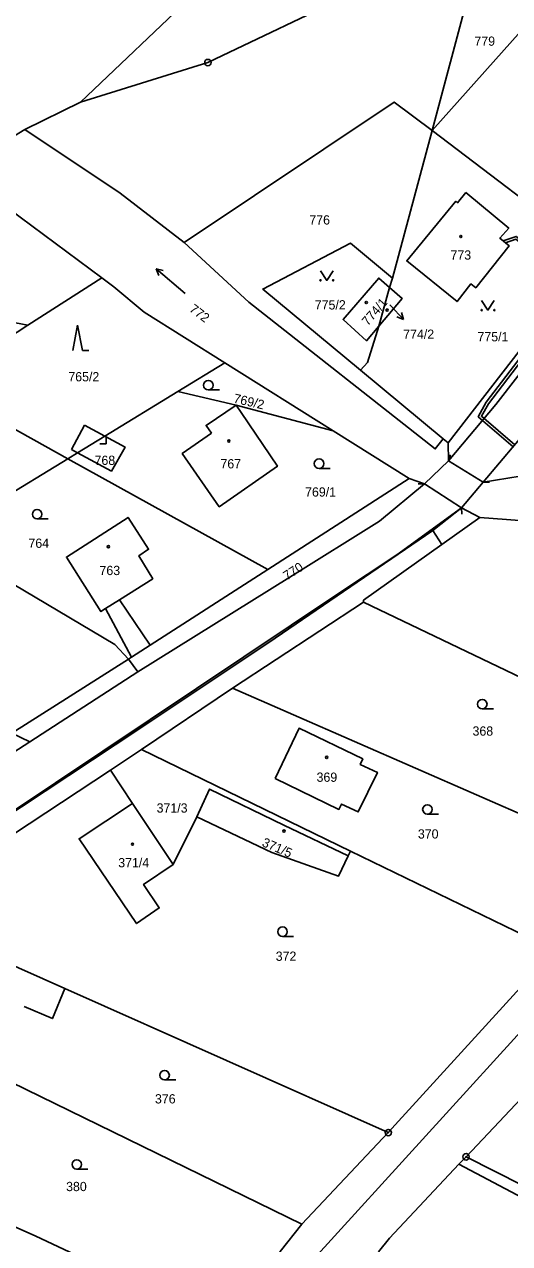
# Model space of a CAD drawing. Extents: x -587171 to -555306, y -1167727 to -1074732.
# Drawn here: x -560683.2 to -560606.6, y -1078329.1 to -1078136.7 of the extents above; entities that cross this region are included whole.
import ezdxf

# ---------------------------------------------------------------- set-up
doc = ezdxf.new("R2010")
doc.units = 0
for name, color, linetype in [('Hranice parcel', 7, 'Continuous'), ('Parcelní čísla', 7, 'Continuous'), ('Pop  PČ popisy', 7, 'Continuous'), ('Poz předměty', 7, 'Continuous'), ('Vnitřní kresba', 7, 'Continuous'), ('Věcná břemena k části', 7, 'Continuous'), ('Značky bodu BP', 7, 'Continuous'), ('Značky budov', 7, 'Continuous'), ('Značky kultur', 7, 'Continuous')]:
    doc.layers.add(name, color=color, linetype=linetype)

msp = doc.modelspace()

# ---------------------------------------------------------------- linework, layer by layer
at = {"layer": 'Hranice parcel'}
for p, q in [((-560610.78, -1078123.27), (-560618.86, -1078153.49)), ((-560599.98, -1078132.35), (-560618.86, -1078153.49)), ((-560683.18, -1078153.32), (-560674.38, -1078149)), ((-560625.08, -1078176.75), (-560618.86, -1078153.49)), ((-560670.98, -1078176.74), (-560693.82, -1078159.78)), ((-560616.33, -1078202.74), (-560593.21, -1078172.91)), ((-560670.98, -1078176.74), (-560682.66, -1078184.21)), ((-560627.26, -1078184.35), (-560625.59, -1078178.23)), ((-560625.08, -1078176.75), (-560625.59, -1078178.23)), ((-560682.66, -1078184.21), (-560697.37, -1078193.62)), ((-560659.01, -1078194.64), (-560651.59, -1078190.11)), ((-560651.59, -1078190.11), (-560634.45, -1078200.85)), ((-560617.1, -1078202.1), (-560630.14, -1078191.29)), ((-560676.37, -1078205.25), (-560697.37, -1078193.62)), ((-560670.54, -1078201.69), (-560659.01, -1078194.64)), ((-560634.45, -1078200.85), (-560622.47, -1078208.37)), ((-560674.83, -1078204.31), (-560670.54, -1078201.69)), ((-560616.33, -1078202.74), (-560617.1, -1078202.1)), ((-560676.37, -1078205.25), (-560697.03, -1078217.88)), ((-560676.37, -1078205.25), (-560674.83, -1078204.31)), ((-560644.78, -1078222.75), (-560676.37, -1078205.25)), ((-560622.47, -1078208.37), (-560644.78, -1078222.75)), ((-560620.07, -1078209.21), (-560622.47, -1078208.37)), ((-560610.79, -1078208.96), (-560614.19, -1078213.01)), ((-560611.31, -1078214.5), (-560614.19, -1078213.01)), ((-560600.9, -1078215.29), (-560611.31, -1078214.5)), ((-560663.37, -1078234.66), (-560644.78, -1078222.75)), ((-560629.67, -1078227.88), (-560650.35, -1078241.47)), ((-560629.67, -1078227.88), (-560573.72, -1078254.67)), ((-560666.3, -1078236.54), (-560663.37, -1078234.66)), ((-560666.81, -1078236.87), (-560666.3, -1078236.54)), ((-560666.81, -1078236.87), (-560665.29, -1078238.89)), ((-560682.38, -1078249.9), (-560665.29, -1078238.89)), ((-560650.35, -1078241.47), (-560664.75, -1078251.14)), ((-560650.35, -1078241.47), (-560587.14, -1078269.06)), ((-560698.04, -1078259.98), (-560682.38, -1078249.9)), ((-560664.75, -1078251.14), (-560669.63, -1078254.36)), ((-560664.75, -1078251.14), (-560631.72, -1078267.16)), ((-560669.63, -1078254.36), (-560699.58, -1078274.12)), ((-560666.15, -1078259.62), (-560669.63, -1078254.36)), ((-560666.15, -1078259.62), (-560659.76, -1078269.27)), ((-560655.99, -1078261.72), (-560659.76, -1078269.27)), ((-560631.72, -1078267.16), (-560632.08, -1078267.89)), ((-560631.72, -1078267.16), (-560599.53, -1078282.77)), ((-560691.6, -1078282.24), (-560676.82, -1078288.83)), ((-560625.76, -1078311.56), (-560599.53, -1078282.77)), ((-560676.82, -1078288.83), (-560625.76, -1078311.56)), ((-560588.9, -1078289.27), (-560613.49, -1078315.38)), ((-560691.79, -1078300.48), (-560639.44, -1078326)), ((-560639.44, -1078326), (-560625.76, -1078311.56)), ((-560614.6, -1078316.55), (-560613.49, -1078315.38))]:
    msp.add_line(p, q, dxfattribs=at)
for points in [[(-560364.68, -1077894.4), (-560366.71, -1077894.44), (-560368.49, -1077895.33), (-560369.63, -1077896.38), (-560417.05, -1077958.08), (-560457.78, -1078010.82), (-560494.61, -1078058.79), (-560557.78, -1078140.57), (-560603.03, -1078199.81), (-560610.79, -1078208.96)], [(-560674.38, -1078149), (-560656.3, -1078131.82), (-560630.87, -1078105.41), (-560608.7, -1078075.28)], [(-560605.43, -1078079.66), (-560608.74, -1078095.5), (-560617.6, -1078115.38), (-560630.82, -1078131.57), (-560654.26, -1078142.76), (-560674.38, -1078149)], [(-560618.86, -1078153.49), (-560624.82, -1078148.98), (-560658.01, -1078171.17)], [(-560693.82, -1078159.78), (-560691.9, -1078158.62), (-560686.41, -1078155.29), (-560683.18, -1078153.32)], [(-560658.01, -1078171.17), (-560668.12, -1078163.37), (-560683.18, -1078153.32)], [(-560618.86, -1078153.49), (-560594.02, -1078172.3), (-560593.21, -1078172.91)], [(-560613.51, -1078163.27), (-560614.82, -1078164.88), (-560615.09, -1078164.64), (-560622.85, -1078174.04), (-560614.89, -1078180.47), (-560612.72, -1078177.67), (-560611.95, -1078178.29), (-560606.67, -1078171.69), (-560608.17, -1078170.44), (-560606.75, -1078168.87), (-560613.51, -1078163.27)], [(-560617.1, -1078202.1), (-560618.35, -1078203.71), (-560647.77, -1078180.58), (-560658.01, -1078171.17)], [(-560630.14, -1078191.29), (-560645.58, -1078178.48), (-560631.73, -1078171.26), (-560625.08, -1078176.75)], [(-560651.59, -1078190.11), (-560664.3, -1078182.13), (-560669.11, -1078178.12), (-560670.98, -1078176.74)], [(-560625.59, -1078178.23), (-560627.28, -1078176.77), (-560632.89, -1078183.29), (-560629.2, -1078186.63), (-560627.26, -1078184.35)], [(-560627.26, -1078184.35), (-560623.55, -1078179.99), (-560625.59, -1078178.23)], [(-560682.66, -1078184.21), (-560708.94, -1078179.22), (-560716.35, -1078183.1)], [(-560627.26, -1078184.35), (-560629.07, -1078190.05), (-560630.14, -1078191.29)], [(-560634.45, -1078200.85), (-560649.79, -1078196.79), (-560659.01, -1078194.64)], [(-560653.68, -1078201.24), (-560658.3, -1078204.45), (-560652.47, -1078212.84), (-560643.27, -1078206.44), (-560648.99, -1078197.98), (-560649.79, -1078196.79), (-560654.54, -1078200.01), (-560653.68, -1078201.24)], [(-560674.83, -1078204.31), (-560669.5, -1078207.2), (-560667.33, -1078203.41), (-560670.54, -1078201.69)], [(-560620.07, -1078209.21), (-560616.23, -1078205.58), (-560616.33, -1078202.74)], [(-560665.29, -1078238.89), (-560641.31, -1078223.92), (-560627.17, -1078215.1), (-560620.07, -1078209.21)], [(-560610.79, -1078208.96), (-560606.86, -1078208.33), (-560604.94, -1078208.02)], [(-560682.38, -1078249.9), (-560685.21, -1078248.55), (-560765.59, -1078210.1)], [(-560614.19, -1078213.01), (-560624.44, -1078220.41), (-560633.62, -1078226.53), (-560693.33, -1078266.36), (-560745.67, -1078300.51), (-560764.56, -1078312.94), (-560776.56, -1078320.84), (-560789.02, -1078328.98), (-560788.94, -1078329.13)], [(-560614.19, -1078213.01), (-560618.74, -1078216.59), (-560643.65, -1078233.58), (-560665.15, -1078247.94), (-560691.05, -1078265.01), (-560721.21, -1078284.77), (-560745.49, -1078300.66), (-560767.21, -1078314.92), (-560788.94, -1078329.13)], [(-560663.37, -1078234.66), (-560668.21, -1078227.51), (-560662.96, -1078224.19), (-560665.18, -1078220.58), (-560663.61, -1078219.54), (-560666.85, -1078214.51), (-560676.59, -1078220.77), (-560671.14, -1078229.36), (-560670.4, -1078228.89), (-560666.3, -1078236.54)], [(-560611.31, -1078214.5), (-560617.29, -1078218.76), (-560629.67, -1078227.59), (-560629.67, -1078227.88)], [(-560686.84, -1078223.94), (-560668.95, -1078234.57), (-560666.81, -1078236.87)], [(-560643.61, -1078255.69), (-560633.56, -1078260.57), (-560633.17, -1078259.74), (-560630.52, -1078260.96), (-560627.49, -1078254.73), (-560630.2, -1078253.48), (-560629.79, -1078252.62), (-560639.85, -1078247.77), (-560643.61, -1078255.69)], [(-560655.99, -1078261.72), (-560653.98, -1078257.38), (-560642.25, -1078263.05), (-560632.08, -1078267.89)], [(-560659.76, -1078269.27), (-560664.41, -1078272.4), (-560661.93, -1078276.11), (-560665.51, -1078278.59), (-560674.59, -1078265.21), (-560666.15, -1078259.62)], [(-560632.08, -1078267.89), (-560633.64, -1078271.12), (-560644.18, -1078267.38), (-560655.99, -1078261.72)], [(-560683.29, -1078291.65), (-560678.8, -1078293.56), (-560676.82, -1078288.83)], [(-560627.29, -1078330.35), (-560625.56, -1078328.2), (-560614.6, -1078316.55)], [(-560385.98, -1078420.93), (-560440.99, -1078396.48), (-560509.19, -1078367.57), (-560529.93, -1078357.83), (-560576.18, -1078336.84), (-560614.6, -1078316.55)], [(-560613.49, -1078315.38), (-560586.49, -1078329.01), (-560584.41, -1078326.77)], [(-560701.89, -1078318.79), (-560681.43, -1078327.92), (-560659.37, -1078338.27), (-560653.21, -1078341.45)], [(-560653.21, -1078341.45), (-560642.85, -1078330.31), (-560639.44, -1078326)]]:
    msp.add_lwpolyline(points, dxfattribs=at)
at = {"layer": 'Pop  PČ popisy'}
for p, q in [((-560625.5, -1078180.97), (-560625.41, -1078181.07)), ((-560625.41, -1078181.07), (-560623.36, -1078183.27)), ((-560623.36, -1078183.27), (-560623.68, -1078182.19)), ((-560623.36, -1078183.27), (-560624.41, -1078182.87))]:
    msp.add_line(p, q, dxfattribs=at)
at = {"layer": 'Poz předměty'}
msp.add_line((-560637.46, -1078331.41), (-560583.59, -1078272.23), dxfattribs=at)
at = {"layer": 'Vnitřní kresba'}
for p, q in [((-560562.6, -1078136.93), (-560608.77, -1078196.7)), ((-560608.77, -1078196.7), (-560616.23, -1078205.58)), ((-560673.73, -1078199.97), (-560675.8, -1078203.79)), ((-560670.54, -1078201.69), (-560673.73, -1078199.97)), ((-560675.8, -1078203.79), (-560674.83, -1078204.31)), ((-560615.95, -1078204.62), (-560616.23, -1078205.58)), ((-560616.23, -1078205.58), (-560610.79, -1078208.96)), ((-560621.07, -1078209.23), (-560620.07, -1078209.21)), ((-560614.19, -1078213.01), (-560620.07, -1078209.21)), ((-560609.79, -1078208.94), (-560610.79, -1078208.96)), ((-560614.17, -1078214.01), (-560614.19, -1078213.01)), ((-560618.74, -1078216.59), (-560617.29, -1078218.76)), ((-560670.4, -1078228.89), (-560668.21, -1078227.51)), ((-560685.21, -1078248.55), (-560666.81, -1078236.87))]:
    msp.add_line(p, q, dxfattribs=at)
at = {"layer": 'Věcná břemena k části'}
msp.add_lwpolyline([(-560597.68, -1078176.78), (-560596.64, -1078177.33), (-560596.39, -1078177.01), (-560597.46, -1078176.45), (-560605.56, -1078170.19), (-560607.64, -1078170.88), (-560607.28, -1078171.18), (-560605.63, -1078170.63)], close=True, dxfattribs=at)
for points in [[(-560596, -1078177.67), (-560610.3, -1078196.35), (-560611.56, -1078198.63), (-560606.04, -1078203.36)], [(-560605.78, -1078203.05), (-560611.05, -1078198.54), (-560609.96, -1078196.57), (-560595.54, -1078177.72)]]:
    msp.add_lwpolyline(points, dxfattribs=at)
at = {"layer": 'Značky bodu BP'}
for centre, radius in [((-560654.26, -1078142.76), 0.5), ((-560654.26, -1078142.76), 0.0303), ((-560625.76, -1078311.56), 0.5), ((-560625.76, -1078311.56), 0.0303), ((-560613.49, -1078315.38), 0.5), ((-560613.49, -1078315.38), 0.0303)]:
    msp.add_circle(centre, radius, dxfattribs=at)
at = {"layer": 'Značky budov'}
for centre in [(-560614.31, -1078170.19), (-560629.24, -1078180.61), (-560625.95, -1078181.81), (-560650.95, -1078202.47), (-560669.96, -1078219.14), (-560635.49, -1078252.37), (-560642.23, -1078263.99), (-560666.15, -1078266.06)]:
    msp.add_circle(centre, 0.175, dxfattribs=at)
at = {"layer": 'Značky kultur'}
for p, q in [((-560657.82, -1078179.17), (-560662.42, -1078175.31)), ((-560662.42, -1078175.31), (-560661.99, -1078176.33)), ((-560662.42, -1078175.31), (-560661.34, -1078175.56)), ((-560674.82, -1078184.19), (-560675.57, -1078188.19)), ((-560674.07, -1078188.19), (-560674.82, -1078184.19)), ((-560674.07, -1078188.19), (-560673.07, -1078188.19)), ((-560654.18, -1078194.41), (-560652.43, -1078194.41)), ((-560671.33, -1078202.88), (-560670.33, -1078202.88)), ((-560670.33, -1078202.88), (-560670.33, -1078201.88)), ((-560636.7, -1078206.78), (-560634.95, -1078206.78)), ((-560681.22, -1078214.76), (-560679.47, -1078214.76)), ((-560610.92, -1078244.72), (-560609.17, -1078244.72)), ((-560619.59, -1078261.33), (-560617.84, -1078261.33)), ((-560642.46, -1078280.61), (-560640.71, -1078280.61)), ((-560661.09, -1078303.25), (-560659.34, -1078303.25)), ((-560674.96, -1078317.33), (-560673.21, -1078317.33))]:
    msp.add_line(p, q, dxfattribs=at)
for points in [[(-560636.47, -1078175.62), (-560635.47, -1078177.12), (-560634.47, -1078175.62)], [(-560611.02, -1078180.31), (-560610.02, -1078181.81), (-560609.02, -1078180.31)]]:
    msp.add_lwpolyline(points, dxfattribs=at)
for centre, radius in [((-560636.47, -1078177.12), 0.1), ((-560634.47, -1078177.12), 0.1), ((-560611.02, -1078181.81), 0.1), ((-560609.02, -1078181.81), 0.1), ((-560654.18, -1078193.66), 0.75), ((-560636.7, -1078206.03), 0.75), ((-560681.22, -1078214.01), 0.75), ((-560610.92, -1078243.97), 0.75), ((-560619.59, -1078260.58), 0.75), ((-560642.46, -1078279.86), 0.75), ((-560661.09, -1078302.5), 0.75), ((-560674.96, -1078316.58), 0.75)]:
    msp.add_circle(centre, radius, dxfattribs=at)

# ---------------------------------------------------------------- texts
at = {"layer": 'Parcelní čísla'}
for s, p in [('779', (-560612.16, -1078140.11)), ('776', (-560638.23, -1078168.31)), ('773', (-560615.94, -1078173.85)), ('775/2', (-560637.37, -1078181.71)), ('774/2', (-560623.41, -1078186.34)), ('775/1', (-560611.68, -1078186.74)), ('765/2', (-560676.29, -1078193.05)), ('768', (-560672.15, -1078206.23)), ('767', (-560652.27, -1078206.78)), ('769/1', (-560638.9, -1078211.23)), ('764', (-560682.59, -1078219.31)), ('763', (-560671.37, -1078223.61)), ('368', (-560612.46, -1078248.94)), ('369', (-560637.09, -1078256.22)), ('371/3', (-560662.35, -1078261.08)), ('370', (-560621.09, -1078265.17)), ('371/4', (-560668.41, -1078269.71)), ('372', (-560643.54, -1078284.46)), ('376', (-560662.61, -1078306.96)), ('380', (-560676.64, -1078320.79))]:
    msp.add_text(s, height=1.46, dxfattribs=at).set_placement(p)
for s, rotation, p in [('774/1', 49, (-560629, -1078184.39)), ('772', 323, (-560657.3, -1078181.9)), ('769/2', 347, (-560650.3, -1078196.39)), ('770', 33, (-560641.77, -1078224.49)), ('371/5', 337, (-560645.83, -1078266.32))]:
    msp.add_text(s, height=1.46, rotation=rotation, dxfattribs=at).set_placement(p)

doc.saveas('drawing.dxf')
